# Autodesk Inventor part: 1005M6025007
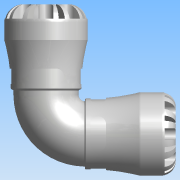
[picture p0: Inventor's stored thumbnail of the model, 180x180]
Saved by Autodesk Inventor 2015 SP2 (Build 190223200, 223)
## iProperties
Created: 2016-12
Part Number: 1005M6025007
Material: PVC-Piping
Description: PLASSON 90° ELBOW METRIC TO IMPERIAL 25X3/4" SERIES 1
Document SubType Name: Modeling
Designer: KIM
Mass: 664.223 g
Surface Area: 733.008 cm^2
Volume: 474.445 cm^3
Density: 1.4 g/cm^3
Appearance: Smooth - White
Author: KIM
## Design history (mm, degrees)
derived "1005M.ipt"
feature "Solid1::1005M.ipt"
tag "TaggingFeature1"
body "Solid1"
other parameters: "d9" = 7.875, "d11" = 47, "d12" = 31.25, "d230" = 47, "d231" = 26.67, "d232" = 10.165, "d1" = 20.16, "d2" = 25, "d3" = 31.25, "d4" = 47, "d8" = 39.95, "d13" = 6.3, "d14" = 6.3, "d15" = 0, "d17" = 360 deg, "d19" = 8 deg, "d20" = 0.5, "d21" = 0.5, "d22" = 8 deg, "d24" = 0, "d26" = 360 deg, "d33" = 4.7, "d43" = 36.66, "d51" = 0.47, "d54" = 8.75, "d55" = 5.5, "d57" = 12.348, "d58" = 0, "d74" = 0, "d77" = 2.08333, "d78" = 48, "d82" = 0.5, "d115" = 360 deg, "d207" = 90 deg, "d209" = 20.16, "d210" = 19.05, "d211" = 26.67, "d212" = 47, "d213" = 39.95, "d215" = 36.66, "d216" = 1.5875, "d217" = 48, "d226" = 48, "d228" = 7.4375, "d229" = 8.132, "d233" = 8.132, "d234" = 0, "d236" = 360 deg, "d238" = 8 deg, "d239" = 8 deg, "d240" = 0.5, "d241" = 0.5, "d243" = 0, "d245" = 360 deg, "d248" = 2.88, "d249" = 2.88, "d250" = 7.4375, "d252" = 8.75, "d253" = 5.75, "d254" = 12.348, "d255" = 0, "d257" = 360 deg, "d259" = 0.5, "d261" = 0, "d262" = 0.94, "d268" = 0, "d269" = 73, "d270" = 2.88, "d271" = 21.9725, "d272" = 73, "d285" = 0, "d286" = 0, "d288" = 1.645, "d290" = 30 deg, "d291" = 0.47, "d_" = 25, "E_" = 47, "l_" = 48, "A_1" = 73, "A_" = 73, "d_1" = 19.05, "E_1" = 47, "l_1" = 48
